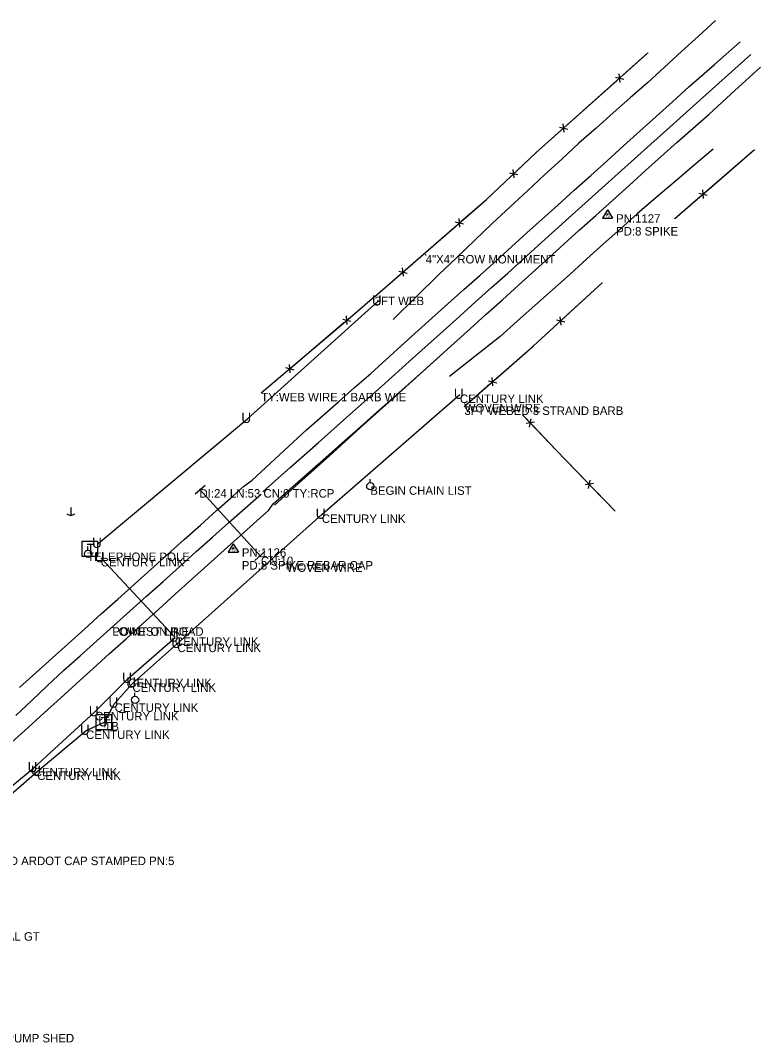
# Model space of a CAD drawing. Extents: x 1568433 to 1572450, y 731863 to 733450.
# Drawn here: x 1572016 to 1572450, y 732531 to 733131 of the extents above; entities that cross this region are included whole.
import ezdxf

# ---------------------------------------------------------------- set-up
doc = ezdxf.new("R2010")
doc.units = 0
for name, color, linetype in [('Default', 7, 'Continuous'), ('S_CROSS_DRAIN', 7, 'Continuous'), ('S_CROSS_DRAIN_ANNOT', 7, 'Continuous'), ('S_DITCHLINE', 7, 'Continuous'), ('S_DRG_PT_SYM', 7, 'Continuous'), ('S_EDGE_PAVEMENT', 7, 'Continuous'), ('S_ELECTRIC_UTILITIES_ANNOT', 7, 'Continuous'), ('S_FENCE', 7, 'Continuous'), ('S_FENCE_ANNOT', 7, 'Continuous'), ('S_GATE_ANNOT', 7, 'Continuous'), ('S_HEADWALL', 7, 'Continuous'), ('S_MISC_STRUCTURES_ANNOT', 7, 'Continuous'), ('S_MSC_PT_SYM', 7, 'Continuous'), ('S_PAVEMENT_CROWN', 7, 'Continuous'), ('S_PRIMARY_CTL_ANNOT', 7, 'Continuous'), ('S_SECONDARY_CTL', 7, 'Continuous'), ('S_SECONDARY_CTL_ANNOT', 7, 'Continuous'), ('S_SHOULDER', 7, 'Continuous'), ('S_SURVEY_TEXT_ANNOT', 7, 'Continuous'), ('S_TELEPHONE_UTILITIES', 7, 'Continuous'), ('S_TELEPHONE_UTILITIES_ANNOT', 7, 'Continuous'), ('S_UNDERGROUND_CABLE', 7, 'Continuous'), ('S_UNDERGROUND_CABLE_ANNOT', 7, 'Continuous'), ('S_UTILITY_POLE', 7, 'Continuous'), ('S_UTILITY_POLE_ANNOT', 7, 'Continuous'), ('S_UTL_PT_SYM', 7, 'Continuous')]:
    doc.layers.add(name, color=color, linetype=linetype)

msp = doc.modelspace()

# ---------------------------------------------------------------- linework, layer by layer
at = {"layer": 'S_CROSS_DRAIN'}
msp.add_line((1572121.03, 732855.99), (1572157.1, 732816.38), dxfattribs=at)
at = {"layer": 'S_DITCHLINE'}
for points in [[(1572423.81, 733130.99), (1572413.8, 733121.86), (1572403.79, 733112.72), (1572393.78, 733103.59), (1572383.77, 733094.46), (1572373.74, 733085.58), (1572363.72, 733076.71), (1572353.69, 733067.83), (1572343.66, 733058.96), (1572333.57, 733049.64), (1572323.47, 733040.32), (1572313.38, 733031.01), (1572303.28, 733021.69), (1572292.83, 733011.77), (1572282.37, 733001.85), (1572271.92, 732991.93), (1572261.46, 732982.01), (1572248.07, 732968.78), (1572234.69, 732955.54)], [(1572422.33, 733055.47), (1572411.19, 733045.98), (1572400.06, 733036.5), (1572388.92, 733027.02), (1572377.78, 733017.53), (1572367.95, 733008.7), (1572358.11, 732999.86), (1572348.27, 732991.03), (1572338.44, 732982.2), (1572328.12, 732973), (1572317.8, 732963.81), (1572307.48, 732954.61), (1572297.16, 732945.41), (1572282.47, 732933.73), (1572267.77, 732922.04)]]:
    msp.add_lwpolyline(points, dxfattribs=at)
at = {"layer": 'S_DRG_PT_SYM'}
for points in [[(1572121.03, 732855.99), (1572121.03, 732856.04), (1572121.03, 732855.99), (1572120.98, 732855.99), (1572121.03, 732855.99), (1572121.03, 732855.94), (1572121.03, 732855.99), (1572121.08, 732855.99)], [(1572157.1, 732816.38), (1572157.1, 732816.43), (1572157.1, 732816.38), (1572157.05, 732816.38), (1572157.1, 732816.38), (1572157.1, 732816.33), (1572157.1, 732816.38), (1572157.15, 732816.38)]]:
    msp.add_lwpolyline(points, dxfattribs=at)
at = {"layer": 'S_EDGE_PAVEMENT'}
for points in [[(1572152, 732861.31), (1572167.9, 732876.02), (1572183.8, 732890.74), (1572193.22, 732899.01), (1572202.63, 732907.29), (1572212.05, 732915.56), (1572221.46, 732923.83), (1572239.38, 732940.05), (1572257.3, 732956.27), (1572266.73, 732964.7), (1572276.17, 732973.14), (1572285.6, 732981.58), (1572295.03, 732990.01), (1572313.13, 733006.32), (1572331.23, 733022.63), (1572340.89, 733031.31), (1572350.54, 733039.98), (1572360.2, 733048.65), (1572369.86, 733057.32), (1572379.42, 733065.98), (1572388.99, 733074.64), (1572398.55, 733083.3), (1572408.12, 733091.95), (1572423.13, 733105.15), (1572438.14, 733118.34)], [(1572164.32, 732847.35), (1572180.6, 732861.78), (1572196.88, 732876.21), (1572206.29, 732884.52), (1572215.7, 732892.83), (1572225.1, 732901.14), (1572234.51, 732909.45), (1572252.46, 732925.49), (1572270.41, 732941.54), (1572279.84, 732950.05), (1572289.27, 732958.56), (1572298.7, 732967.06), (1572308.13, 732975.57), (1572325.96, 732991.71), (1572343.79, 733007.84), (1572353.54, 733016.61), (1572363.28, 733025.38), (1572373.03, 733034.14), (1572382.78, 733042.91), (1572401.36, 733059.49), (1572419.95, 733076.07), (1572435.07, 733089.79), (1572450.19, 733103.51)], [(1572146.88, 732857.5), (1572152, 732861.31)], [(1572015.35, 732739.59), (1572024.93, 732748.21), (1572034.51, 732756.83), (1572044.15, 732765.47), (1572053.8, 732774.11), (1572063.44, 732782.75), (1572073.09, 732791.39), (1572082.83, 732800.15), (1572092.58, 732808.91), (1572102.32, 732817.67), (1572112.06, 732826.43), (1572121.58, 732834.93), (1572131.1, 732843.42), (1572140.62, 732851.92), (1572146.88, 732857.5)], [(1572010.94, 732707.6), (1572020.43, 732716.21), (1572029.92, 732724.82), (1572039.41, 732733.43), (1572048.9, 732742.04), (1572058.58, 732750.77), (1572068.25, 732759.5), (1572077.93, 732768.22), (1572087.6, 732776.95), (1572097.19, 732785.63), (1572106.78, 732794.3), (1572116.36, 732802.98), (1572125.95, 732811.66), (1572135.5, 732820.22), (1572145.05, 732828.78), (1572154.6, 732837.34), (1572161.42, 732843.45)], [(1572161.42, 732843.45), (1572164.32, 732847.35)]]:
    msp.add_lwpolyline(points, dxfattribs=at)
at = {"layer": 'S_FENCE'}
for p, q in [((1572318.36, 733053.22), (1572384.02, 733111.9)), ((1572365.09, 733097.73), (1572369.95, 733096.58)), ((1572367.82, 733094.67), (1572367.23, 733099.64)), ((1572335.04, 733065.38), (1572334.45, 733070.34)), ((1572332.31, 733068.43), (1572337.18, 733067.29)), ((1572289.33, 733025.96), (1572318.36, 733053.22)), ((1572399.91, 733014.7), (1572446.59, 733055.22)), ((1572302.92, 733041.53), (1572307.82, 733040.51)), ((1572305.73, 733038.55), (1572305.02, 733043.5)), ((1572414.07, 733029.71), (1572418.92, 733028.49)), ((1572416.76, 733026.61), (1572416.24, 733031.58)), ((1572223.82, 732968.94), (1572289.33, 733025.96)), ((1572271.12, 733012.82), (1572275.97, 733011.61)), ((1572273.81, 733009.73), (1572273.28, 733014.7)), ((1572237.97, 732983.97), (1572242.82, 732982.76)), ((1572240.66, 732980.88), (1572240.13, 732985.85)), ((1572316.73, 732939.83), (1572357.23, 732976.97)), ((1572208.02, 732955.61), (1572223.68, 732969.11)), ((1572207.71, 732952.66), (1572207.24, 732957.64)), ((1572207.71, 732952.66), (1572207.24, 732957.64)), ((1572333.26, 732952.22), (1572332.61, 732957.17)), ((1572157.24, 732912.46), (1572208.02, 732955.61)), ((1572205.06, 732955.79), (1572209.9, 732954.52)), ((1572205.06, 732955.79), (1572209.9, 732954.52)), ((1572330.49, 732955.23), (1572335.38, 732954.15)), ((1572276.4, 732904.5), (1572316.73, 732939.83)), ((1572171.57, 732927.33), (1572176.41, 732926.06)), ((1572171.57, 732927.33), (1572176.41, 732926.06)), ((1572174.22, 732924.2), (1572173.75, 732929.18)), ((1572174.22, 732924.2), (1572173.75, 732929.18)), ((1572293.22, 732916.51), (1572292.68, 732921.48)), ((1572290.52, 732919.59), (1572295.38, 732918.4)), ((1572330.25, 732878.92), (1572310.79, 732899.45)), ((1572314.64, 732892.42), (1572315.64, 732897.31)), ((1572317.61, 732895.23), (1572312.67, 732894.5)), ((1572364.94, 732843.07), (1572330.25, 732878.92)), ((1572349.19, 732856.4), (1572350.14, 732861.31)), ((1572352.13, 732859.25), (1572347.2, 732858.46))]:
    msp.add_line(p, q, dxfattribs=at)
for points in [[(1572368.59, 733098.11), (1572383.49, 733111.43)], [(1572336.23, 733069.19), (1572366.03, 733095.82)], [(1572318.36, 733053.22), (1572333.25, 733066.53)], [(1572306.83, 733042.39), (1572318.36, 733053.22)], [(1572418, 733030.41), (1572446.59, 733055.22)], [(1572289.33, 733025.96), (1572303.91, 733039.65)], [(1572274.62, 733013.16), (1572289.33, 733025.96)], [(1572399.91, 733014.7), (1572414.99, 733027.79)], [(1572241.9, 732984.68), (1572272.04, 733010.91)], [(1572223.82, 732968.94), (1572238.89, 732982.05)], [(1572334.41, 732956.05), (1572357.23, 732976.97)], [(1572175.51, 732927.99), (1572205.96, 732953.86)], [(1572175.51, 732927.99), (1572205.96, 732953.86)], [(1572316.73, 732939.83), (1572331.46, 732953.34)], [(1572294.45, 732920.31), (1572316.73, 732939.83)], [(1572157.24, 732912.46), (1572172.47, 732925.4)], [(1572157.24, 732912.46), (1572172.47, 732925.4)], [(1572276.4, 732904.5), (1572291.45, 732917.68)], [(1572313.76, 732896.31), (1572310.79, 732899.45)], [(1572330.25, 732878.92), (1572316.51, 732893.42)], [(1572348.28, 732860.29), (1572330.25, 732878.92)], [(1572364.94, 732843.07), (1572351.05, 732857.42)]]:
    msp.add_lwpolyline(points, dxfattribs=at)
at = {"layer": 'S_HEADWALL'}
for points in [[(1572124.33, 732858.16), (1572118.44, 732853)], [(1572153.58, 732814.1), (1572159.43, 732819.44)]]:
    msp.add_lwpolyline(points, dxfattribs=at)
at = {"layer": 'S_MSC_PT_SYM'}
for points in [[(1572384.02, 733111.9), (1572384.02, 733111.95), (1572384.02, 733111.9), (1572383.97, 733111.9), (1572384.02, 733111.9), (1572384.02, 733111.85), (1572384.02, 733111.9), (1572384.07, 733111.9)], [(1572318.36, 733053.22), (1572318.36, 733053.27), (1572318.36, 733053.22), (1572318.31, 733053.22), (1572318.36, 733053.22), (1572318.36, 733053.17), (1572318.36, 733053.22), (1572318.41, 733053.22)], [(1572446.59, 733055.22), (1572446.59, 733055.27), (1572446.59, 733055.22), (1572446.54, 733055.22), (1572446.59, 733055.22), (1572446.59, 733055.17), (1572446.59, 733055.22), (1572446.64, 733055.22)], [(1572289.33, 733025.96), (1572289.33, 733026.01), (1572289.33, 733025.96), (1572289.28, 733025.96), (1572289.33, 733025.96), (1572289.33, 733025.91), (1572289.33, 733025.96), (1572289.38, 733025.96)], [(1572399.91, 733014.7), (1572399.91, 733014.75), (1572399.91, 733014.7), (1572399.86, 733014.7), (1572399.91, 733014.7), (1572399.91, 733014.65), (1572399.91, 733014.7), (1572399.96, 733014.7)], [(1572253.77, 732993.4), (1572253.77, 732993.45), (1572253.77, 732993.4), (1572253.72, 732993.4), (1572253.77, 732993.4), (1572253.77, 732993.35), (1572253.77, 732993.4), (1572253.82, 732993.4)], [(1572241.5, 732984.46), (1572241.5, 732984.51), (1572241.5, 732984.46), (1572241.45, 732984.46), (1572241.5, 732984.46), (1572241.5, 732984.41), (1572241.5, 732984.46), (1572241.55, 732984.46)], [(1572357.23, 732976.97), (1572357.23, 732977.02), (1572357.23, 732976.97), (1572357.18, 732976.97), (1572357.23, 732976.97), (1572357.23, 732976.92), (1572357.23, 732976.97), (1572357.28, 732976.97)], [(1572223.82, 732968.94), (1572223.82, 732968.99), (1572223.82, 732968.94), (1572223.77, 732968.94), (1572223.82, 732968.94), (1572223.82, 732968.89), (1572223.82, 732968.94), (1572223.87, 732968.94)], [(1572208.02, 732955.61), (1572208.02, 732955.66), (1572208.02, 732955.61), (1572207.97, 732955.61), (1572208.02, 732955.61), (1572208.02, 732955.56), (1572208.02, 732955.61), (1572208.07, 732955.61)], [(1572316.73, 732939.83), (1572316.73, 732939.88), (1572316.73, 732939.83), (1572316.68, 732939.83), (1572316.73, 732939.83), (1572316.73, 732939.78), (1572316.73, 732939.83), (1572316.78, 732939.83)], [(1572157.24, 732912.46), (1572157.24, 732912.51), (1572157.24, 732912.46), (1572157.19, 732912.46), (1572157.24, 732912.46), (1572157.24, 732912.41), (1572157.24, 732912.46), (1572157.29, 732912.46)], [(1572276.4, 732904.5), (1572276.4, 732904.55), (1572276.4, 732904.5), (1572276.35, 732904.5), (1572276.4, 732904.5), (1572276.4, 732904.45), (1572276.4, 732904.5), (1572276.45, 732904.5)], [(1572276.61, 732906.02), (1572276.61, 732906.07), (1572276.61, 732906.02), (1572276.56, 732906.02), (1572276.61, 732906.02), (1572276.61, 732905.97), (1572276.61, 732906.02), (1572276.66, 732906.02)], [(1572310.79, 732899.45), (1572310.79, 732899.5), (1572310.79, 732899.45), (1572310.74, 732899.45), (1572310.79, 732899.45), (1572310.79, 732899.4), (1572310.79, 732899.45), (1572310.84, 732899.45)], [(1572330.25, 732878.92), (1572330.25, 732878.97), (1572330.25, 732878.92), (1572330.2, 732878.92), (1572330.25, 732878.92), (1572330.25, 732878.87), (1572330.25, 732878.92), (1572330.3, 732878.92)], [(1572364.94, 732843.07), (1572364.94, 732843.12), (1572364.94, 732843.07), (1572364.89, 732843.07), (1572364.94, 732843.07), (1572364.94, 732843.02), (1572364.94, 732843.07), (1572364.99, 732843.07)], [(1572172.15, 732812.46), (1572172.15, 732812.51), (1572172.15, 732812.46), (1572172.1, 732812.46), (1572172.15, 732812.46), (1572172.15, 732812.41), (1572172.15, 732812.46), (1572172.2, 732812.46)], [(1572069.94, 732774.95), (1572069.94, 732775), (1572069.94, 732774.95), (1572069.89, 732774.95), (1572069.94, 732774.95), (1572069.94, 732774.9), (1572069.94, 732774.95), (1572069.99, 732774.95)], [(1572070.11, 732774.91), (1572070.11, 732774.96), (1572070.11, 732774.91), (1572070.06, 732774.91), (1572070.11, 732774.91), (1572070.11, 732774.86), (1572070.11, 732774.91), (1572070.16, 732774.91)]]:
    msp.add_lwpolyline(points, dxfattribs=at)
at = {"layer": 'S_PAVEMENT_CROWN'}
for points in [[(1572158.26, 732854.34), (1572174.41, 732868.8), (1572190.57, 732883.25), (1572209.21, 732899.75), (1572227.85, 732916.25), (1572246.03, 732932.54), (1572264.21, 732948.83), (1572273.61, 732957.31), (1572283.02, 732965.79), (1572292.43, 732974.26), (1572301.84, 732982.74), (1572319.79, 732998.94), (1572337.74, 733015.15), (1572347.36, 733023.82), (1572356.99, 733032.5), (1572366.61, 733041.17), (1572376.24, 733049.85), (1572385.75, 733058.37), (1572395.26, 733066.9), (1572404.77, 733075.43), (1572414.27, 733083.96), (1572429.41, 733097.53), (1572444.55, 733111.1)], [(1572013.22, 732723.24), (1572022.58, 732731.99), (1572031.94, 732740.74), (1572041.3, 732749.49), (1572051.04, 732758.23), (1572060.78, 732766.97), (1572070.52, 732775.71), (1572080.25, 732784.44), (1572089.98, 732793.16), (1572099.7, 732801.87), (1572109.42, 732810.58), (1572119.15, 732819.3), (1572128.73, 732827.81), (1572138.31, 732836.33), (1572147.89, 732844.84), (1572157.18, 732853.09)]]:
    msp.add_lwpolyline(points, dxfattribs=at)
at = {"layer": 'S_SECONDARY_CTL'}
for p, q in [((1572360.42, 733019.9), (1572357.41, 733014.95)), ((1572360.42, 733019.9), (1572363.37, 733014.95)), ((1572357.41, 733014.95), (1572363.37, 733014.95)), ((1572140.88, 732823.9), (1572137.87, 732818.95)), ((1572137.87, 732818.95), (1572143.83, 732818.95)), ((1572140.88, 732823.9), (1572143.83, 732818.95))]:
    msp.add_line(p, q, dxfattribs=at)
for centre, radius in [((1572360.42, 733017.29), 0.311), ((1572360.42, 733017.29), 0.183), ((1572360.42, 733017.29), 0.103), ((1572140.88, 732821.29), 0.311), ((1572140.88, 732821.29), 0.183), ((1572140.88, 732821.29), 0.103)]:
    msp.add_circle(centre, radius, dxfattribs=at)
at = {"layer": 'S_SHOULDER'}
msp.add_lwpolyline([(1572165, 732846.54), (1572181.14, 732861.07), (1572197.28, 732875.6), (1572215.57, 732892.09), (1572233.85, 732908.57), (1572252.14, 732925.06), (1572270.43, 732941.54), (1572270.41, 732941.54)], dxfattribs=at)
at = {"layer": 'S_TELEPHONE_UTILITIES'}
for points in [[(1572052.24, 732816.4), (1572052.24, 732825.4), (1572061.24, 732825.4), (1572061.24, 732816.4)], [(1572060.49, 732714.81), (1572060.49, 732723.81), (1572069.49, 732723.81), (1572069.49, 732714.81)]]:
    msp.add_lwpolyline(points, close=True, dxfattribs=at)
at = {"layer": 'S_UNDERGROUND_CABLE'}
for p, q in [((1572149.2, 732897.33), (1572225.81, 732966.28)), ((1572192.83, 732841.14), (1572273.85, 732911.5)), ((1572061.58, 732824.03), (1572149.2, 732897.33)), ((1572108.11, 732765.37), (1572192.83, 732841.14)), ((1572106.67, 732769.01), (1572063.12, 732815.64)), ((1572079.26, 732744.83), (1572106.67, 732769.01)), ((1572081.7, 732742.03), (1572108.11, 732765.37)), ((1572059.73, 732725.29), (1572079.26, 732744.83)), ((1572071.26, 732730.29), (1572081.7, 732742.03)), ((1572065.22, 732719.33), (1572071.26, 732730.29)), ((1572023.78, 732692.45), (1572059.73, 732725.29)), ((1572054.5, 732714.39), (1572065.22, 732719.33)), ((1572025.85, 732690.34), (1572054.5, 732714.39)), ((1571944.52, 732626.86), (1572023.78, 732692.45)), ((1571947.87, 732622.6), (1572025.85, 732690.34))]:
    msp.add_line(p, q, dxfattribs=at)
at = {"layer": 'S_UTILITY_POLE'}
for p, q in [((1572221.12, 732859.8), (1572221.12, 732861.91)), ((1572045.48, 732845.31), (1572045.48, 732840.58)), ((1572055.53, 732820.15), (1572055.53, 732822.26)), ((1572083.11, 732734.46), (1572083.11, 732736.56))]:
    msp.add_line(p, q, dxfattribs=at)
for centre in [(1572221.25, 732857.66), (1572055.66, 732818.01), (1572083.23, 732732.31)]:
    msp.add_circle(centre, 2.13, dxfattribs=at)
msp.add_arc((1572045.54, 732844.01), 3.41, 226.39718, 313.60282, dxfattribs=at)
at = {"layer": 'S_UTL_PT_SYM'}
for points in [[(1572069.94, 732774.95), (1572069.94, 732775), (1572069.94, 732774.95), (1572069.89, 732774.95), (1572069.94, 732774.95), (1572069.94, 732774.9), (1572069.94, 732774.95), (1572069.99, 732774.95)], [(1572070.11, 732774.91), (1572070.11, 732774.96), (1572070.11, 732774.91), (1572070.06, 732774.91), (1572070.11, 732774.91), (1572070.11, 732774.86), (1572070.11, 732774.91), (1572070.16, 732774.91)]]:
    msp.add_lwpolyline(points, dxfattribs=at)

# ---------------------------------------------------------------- texts
at = {"layer": 'Default'}
for p in [(1572222.18, 732963.74), (1572270.22, 732908.95), (1572145.57, 732894.78), (1572189.2, 732838.59), (1572057.95, 732821.48), (1572059.49, 732813.1), (1572103.04, 732766.46), (1572104.48, 732762.82), (1572075.63, 732742.29), (1572078.07, 732739.48), (1572056.1, 732722.74), (1572067.63, 732727.74), (1572061.59, 732716.79), (1572050.87, 732711.85), (1572020.15, 732689.9), (1572022.22, 732687.8)]:
    msp.add_text('U', height=6, dxfattribs=at).set_placement(p)
at = {"layer": 'S_CROSS_DRAIN_ANNOT'}
for s, p in [('DI:24 LN:53 CN:0 TY:RCP', (1572121.03, 732850.99)), ('CN:10', (1572157.1, 732811.38))]:
    msp.add_text(s, height=5, dxfattribs=at).set_placement(p)
at = {"layer": 'S_ELECTRIC_UTILITIES_ANNOT'}
msp.add_text('LOWEST LINE', height=5, dxfattribs=at).set_placement((1572069.94, 732769.95))
at = {"layer": 'S_FENCE_ANNOT'}
for s, p in [('3FT WEB', (1572223.82, 732963.94)), ('TY:WEB WIRE 1 BARB WIE', (1572157.24, 732907.46)), ('WOVEN WIRE', (1572276.61, 732901.02)), ('3FT WEBED 3 STRAND BARB', (1572276.4, 732899.5)), ('WOVEN WIRE', (1572172.15, 732807.46))]:
    msp.add_text(s, height=5, dxfattribs=at).set_placement(p)
at = {"layer": 'S_GATE_ANNOT'}
msp.add_text('DOUBLE 10FT LONG METAL GT', height=5, dxfattribs=at).set_placement((1571926.28, 732591.02))
at = {"layer": 'S_MISC_STRUCTURES_ANNOT'}
msp.add_text('4"X4" ROW MONUMENT', height=5, dxfattribs=at).set_placement((1572253.77, 732988.4))
at = {"layer": 'S_PRIMARY_CTL_ANNOT'}
msp.add_text('PD:STD ARDOT CAP STAMPED PN:5', height=5, dxfattribs=at).set_placement((1571990.03, 732635.39))
at = {"layer": 'S_SECONDARY_CTL'}
for p in [(1572359.21, 733015.28), (1572139.68, 732819.28)]:
    msp.add_text('TV', height=1.5, rotation=360, dxfattribs=at).set_placement(p)
at = {"layer": 'S_SECONDARY_CTL_ANNOT'}
for s, p in [('PN:1127', (1572365.42, 733012.29)), ('PD:8 SPIKE', (1572365.42, 733004.79)), ('PN:1126', (1572145.88, 732816.29)), ('PD:8 SPIKE REBAR CAP', (1572145.88, 732808.79))]:
    msp.add_text(s, height=5, dxfattribs=at).set_placement(p)
at = {"layer": 'S_SURVEY_TEXT_ANNOT'}
for s, p in [('POINT ON ROAD', (1572069.94, 732769.95)), ('8FTX10FT PUMP SHED', (1571973.92, 732531.35))]:
    msp.add_text(s, height=5, dxfattribs=at).set_placement(p)
at = {"layer": 'S_TELEPHONE_UTILITIES'}
msp.add_text('T', height=6, rotation=360, dxfattribs=at).set_placement((1572054.81, 732817.9))
msp.add_text('T', height=6, dxfattribs=at).set_placement((1572063.06, 732716.31))
at = {"layer": 'S_TELEPHONE_UTILITIES_ANNOT'}
msp.add_text('TB', height=5, dxfattribs=at).set_placement((1572065.22, 732714.33))
at = {"layer": 'S_UNDERGROUND_CABLE_ANNOT'}
for s, p in [('CENTURY LINK', (1572273.85, 732906.5)), ('CENTURY LINK', (1572192.83, 732836.14)), ('CENTURY LINK', (1572063.12, 732810.64)), ('CENTURY LINK', (1572106.67, 732764.01)), ('CENTURY LINK', (1572108.11, 732760.37)), ('CENTURY LINK', (1572079.26, 732739.83)), ('CENTURY LINK', (1572081.7, 732737.03)), ('CENTURY LINK', (1572071.26, 732725.29)), ('CENTURY LINK', (1572059.73, 732720.29)), ('TB', (1572065.22, 732714.33)), ('CENTURY LINK', (1572054.5, 732709.39)), ('CENTURY LINK', (1572023.78, 732687.45)), ('CENTURY LINK', (1572025.85, 732685.34))]:
    msp.add_text(s, height=5, dxfattribs=at).set_placement(p)
at = {"layer": 'S_UTILITY_POLE_ANNOT'}
for s, p in [('BEGIN CHAIN LIST', (1572221.25, 732852.66)), ('TELEPHONE POLE', (1572055.18, 732813.78))]:
    msp.add_text(s, height=5, dxfattribs=at).set_placement(p)

doc.saveas('drawing.dxf')
